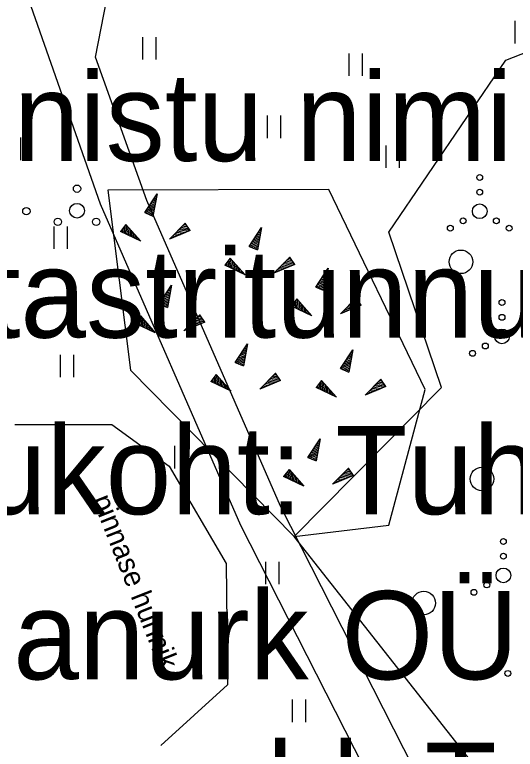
# Model space of a CAD drawing. Extents: x 554947 to 555436, y 6564938 to 6565792.
# Drawn here: x 555027.7 to 555044.71, y 6565611.19 to 6565636.15 of the extents above; entities that cross this region are included whole.
import ezdxf

# ---------------------------------------------------------------- set-up
doc = ezdxf.new("R2010")
doc.units = 0
for name, color, linetype in [('HALJASTUS', 7, 'Continuous'), ('KPKAABEL', 7, 'Continuous'), ('PR_SIDE', 7, 'Continuous'), ('PUU', 7, 'Continuous'), ('RELJEEF', 7, 'Continuous'), ('VORMISTUS_2', 7, 'Continuous')]:
    doc.layers.add(name, color=color, linetype=linetype)

msp = doc.modelspace()

# ---------------------------------------------------------------- linework, layer by layer
at = {"layer": 'HALJASTUS'}
for p, q in [((555044.7, 6565635.942), (555044.7, 6565635.181)), ((555032.047, 6565635.393), (555032.047, 6565634.632)), ((555032.502, 6565635.393), (555032.502, 6565634.632)), ((555039.053, 6565634.836), (555039.053, 6565634.075)), ((555039.508, 6565634.836), (555039.508, 6565634.075)), ((555036.276, 6565632.727), (555036.276, 6565631.965)), ((555036.731, 6565632.727), (555036.731, 6565631.965)), ((555027.9, 6565631.978), (555027.9, 6565631.217)), ((555040.315, 6565631.71), (555040.315, 6565630.949)), ((555040.77, 6565631.71), (555040.77, 6565630.949)), ((555029.028, 6565628.96), (555029.028, 6565628.199)), ((555029.483, 6565628.96), (555029.483, 6565628.199)), ((555029.243, 6565624.6), (555029.243, 6565623.839)), ((555029.698, 6565624.6), (555029.698, 6565623.839)), ((555033.134, 6565621.501), (555033.134, 6565620.74)), ((555033.589, 6565621.501), (555033.589, 6565620.74)), ((555036.221, 6565617.568), (555036.221, 6565616.807)), ((555036.676, 6565617.568), (555036.676, 6565616.807)), ((555037.132, 6565612.883), (555037.132, 6565612.122)), ((555037.587, 6565612.883), (555037.587, 6565612.122))]:
    msp.add_line(p, q, dxfattribs=at)
for points in [[(555057.023, 6565609.855), (555058.586, 6565605.616), (555058.613, 6565599.497), (555057.015, 6565597.532), (555043.839, 6565605.146), (555043.23, 6565610.761), (555037.198, 6565618.427), (555042.201, 6565623.493), (555040.415, 6565628.763), (555044.392, 6565634.613), (555048.032, 6565636.033)], [(555027.704, 6565622.233), (555030.999, 6565622.233), (555032.952, 6565620.81), (555034.891, 6565617.507), (555034.932, 6565613.389), (555032.663, 6565611.321)]]:
    msp.add_lwpolyline(points, dxfattribs=at)
for centre, radius in [((555043.503, 6565630.625), 0.1), ((555043.503, 6565630.125), 0.1), ((555043.503, 6565629.475), 0.25), ((555042.938, 6565629.15), 0.1), ((555044.068, 6565629.15), 0.1), ((555042.503, 6565628.9), 0.1), ((555044.503, 6565628.9), 0.1), ((555042.864, 6565627.758), 0.4), ((555044.26, 6565626.373), 0.1), ((555044.26, 6565625.873), 0.1), ((555044.26, 6565625.223), 0.25), ((555043.695, 6565624.898), 0.1), ((555043.26, 6565624.648), 0.1), ((555043.58, 6565620.38), 0.4), ((555044.307, 6565618.254), 0.1), ((555044.307, 6565617.754), 0.1), ((555044.307, 6565617.104), 0.25), ((555043.742, 6565616.779), 0.1), ((555043.307, 6565616.529), 0.1), ((555041.6, 6565616.164), 0.4), ((555044.458, 6565613.773), 0.1)]:
    msp.add_circle(centre, radius, dxfattribs=at)
at = {"layer": 'KPKAABEL'}
msp.add_lwpolyline([(555022.085, 6565654.913), (555021.622, 6565652.627), (555021.526, 6565649.765), (555022.786, 6565647.231), (555026.485, 6565641.465), (555030.606, 6565629.728), (555035.378, 6565618.813), (555040.844, 6565608.057), (555047.089, 6565597.805), (555053.567, 6565587.292), (555056.073, 6565583.696), (555062.108, 6565572.667), (555068.248, 6565560.982), (555073.771, 6565549.852), (555080.106, 6565537.978), (555085.958, 6565527.605), (555092.403, 6565515.607), (555098.402, 6565504.536), (555104.641, 6565492.438), (555110.839, 6565480.82), (555116.697, 6565469.072), (555121.821, 6565458.116), (555126.894, 6565446.731), (555132.737, 6565435.388)], dxfattribs=at)
at = {"layer": 'PR_SIDE'}
msp.add_lwpolyline([(555074.812, 6565550.025), (555070.293, 6565559.111), (555066.617, 6565567.361), (555061.392, 6565583.505), (555059.394, 6565594.411), (555058.991, 6565594.89), (555051.547, 6565599.57), (555045.662, 6565603.031), (555041.98, 6565609.132), (555036.735, 6565619.454), (555032.194, 6565629.84), (555030.448, 6565634.707), (555030.925, 6565637.158), (555034.991, 6565644.113), (555043.172, 6565658.105), (555043.563, 6565658.774), (555046.326, 6565658.494), (555056.182, 6565651.59), (555064.179, 6565647.804), (555084.437, 6565642.829), (555092.497, 6565648.433), (555092.737, 6565648.737), (555092.881, 6565649.42), (555093.272, 6565650.246)], dxfattribs=at)
at = {"layer": 'PUU'}
for centre, radius in [((555029.819, 6565630.243), 0.125), ((555028.098, 6565629.476), 0.125), ((555029.819, 6565629.493), 0.25), ((555029.169, 6565629.118), 0.125), ((555030.47, 6565629.118), 0.125)]:
    msp.add_circle(centre, radius, dxfattribs=at)
at = {"layer": 'RELJEEF'}
for p, q in [((555032.119, 6565629.429), (555032.539, 6565630.069)), ((555032.369, 6565629.804), (555032.499, 6565629.864)), ((555032.539, 6565630.069), (555032.399, 6565629.314)), ((555032.414, 6565629.879), (555032.514, 6565629.919)), ((555032.464, 6565629.954), (555032.524, 6565629.979)), ((555032.514, 6565630.029), (555032.534, 6565630.039)), ((555032.169, 6565629.504), (555032.454, 6565629.624)), ((555032.219, 6565629.579), (555032.469, 6565629.684)), ((555032.269, 6565629.654), (555032.394, 6565629.709)), ((555032.319, 6565629.729), (555032.489, 6565629.804)), ((555032.394, 6565629.709), (555032.479, 6565629.744)), ((555032.119, 6565629.429), (555032.444, 6565629.569)), ((555032.119, 6565629.429), (555032.399, 6565629.314)), ((555032.119, 6565629.429), (555032.119, 6565629.429)), ((555032.184, 6565629.404), (555032.434, 6565629.509)), ((555032.249, 6565629.374), (555032.424, 6565629.449)), ((555032.319, 6565629.349), (555032.414, 6565629.389)), ((555032.384, 6565629.324), (555032.399, 6565629.329)), ((555031.478, 6565629.028), (555031.293, 6565628.788)), ((555031.348, 6565628.858), (555031.363, 6565628.758)), ((555031.393, 6565628.918), (555031.418, 6565628.733)), ((555031.433, 6565628.973), (555031.468, 6565628.703)), ((555031.478, 6565629.028), (555031.983, 6565628.458)), ((555031.478, 6565629.028), (555031.523, 6565628.678)), ((555031.478, 6565629.028), (555031.478, 6565629.028)), ((555031.538, 6565628.963), (555031.578, 6565628.653)), ((555031.598, 6565628.893), (555031.633, 6565628.628)), ((555032.957, 6565628.523), (555033.497, 6565629.068)), ((555033.667, 6565628.818), (555033.317, 6565628.883)), ((555033.627, 6565628.873), (555033.362, 6565628.928)), ((555033.587, 6565628.933), (555033.402, 6565628.968)), ((555033.547, 6565628.993), (555033.447, 6565629.013)), ((555033.507, 6565629.053), (555033.487, 6565629.053)), ((555033.667, 6565628.818), (555033.497, 6565629.068)), ((555035.669, 6565628.282), (555036.089, 6565628.922)), ((555036.089, 6565628.922), (555035.949, 6565628.167)), ((555036.064, 6565628.882), (555036.084, 6565628.892)), ((555031.983, 6565628.458), (555031.293, 6565628.788)), ((555031.303, 6565628.803), (555031.308, 6565628.783)), ((555031.658, 6565628.828), (555031.673, 6565628.688)), ((555031.673, 6565628.688), (555031.688, 6565628.598)), ((555031.713, 6565628.758), (555031.743, 6565628.573)), ((555031.773, 6565628.693), (555031.793, 6565628.548)), ((555031.833, 6565628.623), (555031.848, 6565628.523)), ((555033.667, 6565628.818), (555032.957, 6565628.523)), ((555033.167, 6565628.608), (555033.062, 6565628.628)), ((555033.247, 6565628.643), (555033.107, 6565628.673)), ((555033.332, 6565628.678), (555033.147, 6565628.713)), ((555033.282, 6565628.738), (555033.192, 6565628.758)), ((555033.497, 6565628.748), (555033.232, 6565628.798)), ((555033.582, 6565628.783), (555033.277, 6565628.843)), ((555033.417, 6565628.713), (555033.282, 6565628.738)), ((555033.667, 6565628.818), (555033.667, 6565628.818)), ((555035.869, 6565628.582), (555036.039, 6565628.657)), ((555035.919, 6565628.657), (555036.049, 6565628.717)), ((555035.964, 6565628.732), (555036.064, 6565628.772)), ((555036.014, 6565628.807), (555036.074, 6565628.832)), ((555031.893, 6565628.558), (555031.903, 6565628.493)), ((555031.953, 6565628.488), (555031.958, 6565628.468)), ((555032.997, 6565628.538), (555032.982, 6565628.543)), ((555033.082, 6565628.573), (555033.022, 6565628.588)), ((555035.669, 6565628.282), (555035.994, 6565628.422)), ((555035.719, 6565628.357), (555036.004, 6565628.477)), ((555035.734, 6565628.257), (555035.984, 6565628.362)), ((555035.769, 6565628.432), (555036.019, 6565628.537)), ((555035.819, 6565628.507), (555035.944, 6565628.562)), ((555035.944, 6565628.562), (555036.029, 6565628.597)), ((555035.669, 6565628.282), (555035.949, 6565628.167)), ((555035.669, 6565628.282), (555035.669, 6565628.282)), ((555035.799, 6565628.227), (555035.974, 6565628.302)), ((555035.869, 6565628.202), (555035.964, 6565628.242)), ((555035.934, 6565628.177), (555035.949, 6565628.182)), ((555035.028, 6565627.881), (555034.843, 6565627.641)), ((555035.028, 6565627.881), (555035.533, 6565627.311)), ((555035.028, 6565627.881), (555035.073, 6565627.531)), ((555035.028, 6565627.881), (555035.028, 6565627.881)), ((555036.507, 6565627.376), (555037.047, 6565627.921)), ((555037.097, 6565627.846), (555036.997, 6565627.866)), ((555037.057, 6565627.906), (555037.037, 6565627.906)), ((555037.217, 6565627.671), (555037.047, 6565627.921)), ((555035.533, 6565627.311), (555034.843, 6565627.641)), ((555034.853, 6565627.656), (555034.858, 6565627.636)), ((555034.898, 6565627.711), (555034.913, 6565627.611)), ((555034.943, 6565627.771), (555034.968, 6565627.586)), ((555034.983, 6565627.826), (555035.018, 6565627.556)), ((555035.088, 6565627.816), (555035.128, 6565627.506)), ((555035.148, 6565627.746), (555035.183, 6565627.481)), ((555035.208, 6565627.681), (555035.223, 6565627.541)), ((555035.263, 6565627.611), (555035.293, 6565627.426)), ((555037.217, 6565627.671), (555036.507, 6565627.376)), ((555036.832, 6565627.591), (555036.742, 6565627.611)), ((555037.047, 6565627.601), (555036.782, 6565627.651)), ((555037.132, 6565627.636), (555036.827, 6565627.696)), ((555037.217, 6565627.671), (555036.867, 6565627.736)), ((555037.177, 6565627.726), (555036.912, 6565627.781)), ((555037.137, 6565627.786), (555036.952, 6565627.821)), ((555037.217, 6565627.671), (555037.217, 6565627.671)), ((555035.223, 6565627.541), (555035.238, 6565627.451)), ((555035.323, 6565627.546), (555035.343, 6565627.401)), ((555035.383, 6565627.476), (555035.398, 6565627.376)), ((555035.443, 6565627.411), (555035.453, 6565627.346)), ((555036.547, 6565627.391), (555036.532, 6565627.396)), ((555036.632, 6565627.426), (555036.572, 6565627.441)), ((555036.717, 6565627.461), (555036.612, 6565627.481)), ((555036.797, 6565627.496), (555036.657, 6565627.526)), ((555036.882, 6565627.531), (555036.697, 6565627.566)), ((555036.967, 6565627.566), (555036.832, 6565627.591)), ((555037.932, 6565626.897), (555038.352, 6565627.537)), ((555038.352, 6565627.537), (555038.212, 6565626.782)), ((555038.227, 6565627.347), (555038.327, 6565627.387)), ((555038.277, 6565627.422), (555038.337, 6565627.447)), ((555038.327, 6565627.497), (555038.347, 6565627.507)), ((555035.503, 6565627.341), (555035.508, 6565627.321)), ((555038.032, 6565627.047), (555038.282, 6565627.152)), ((555038.082, 6565627.122), (555038.207, 6565627.177)), ((555038.132, 6565627.197), (555038.302, 6565627.272)), ((555038.182, 6565627.272), (555038.312, 6565627.332)), ((555038.207, 6565627.177), (555038.292, 6565627.212)), ((555032.612, 6565626.32), (555033.032, 6565626.96)), ((555033.032, 6565626.96), (555032.892, 6565626.205)), ((555032.957, 6565626.845), (555033.017, 6565626.87)), ((555033.007, 6565626.92), (555033.027, 6565626.93)), ((555037.932, 6565626.897), (555038.257, 6565627.037)), ((555037.932, 6565626.897), (555038.212, 6565626.782)), ((555037.932, 6565626.897), (555037.932, 6565626.897)), ((555037.982, 6565626.972), (555038.267, 6565627.092)), ((555037.997, 6565626.872), (555038.247, 6565626.977)), ((555038.062, 6565626.842), (555038.237, 6565626.917)), ((555038.132, 6565626.817), (555038.227, 6565626.857)), ((555032.812, 6565626.62), (555032.982, 6565626.695)), ((555032.862, 6565626.695), (555032.992, 6565626.755)), ((555032.887, 6565626.6), (555032.972, 6565626.635)), ((555032.907, 6565626.77), (555033.007, 6565626.81)), ((555038.197, 6565626.792), (555038.212, 6565626.797)), ((555032.612, 6565626.32), (555032.937, 6565626.46)), ((555032.662, 6565626.395), (555032.947, 6565626.515)), ((555032.677, 6565626.295), (555032.927, 6565626.4)), ((555032.712, 6565626.47), (555032.962, 6565626.575)), ((555032.762, 6565626.545), (555032.887, 6565626.6)), ((555037.291, 6565626.496), (555037.106, 6565626.256)), ((555037.206, 6565626.386), (555037.231, 6565626.201)), ((555037.246, 6565626.441), (555037.281, 6565626.171)), ((555037.291, 6565626.496), (555037.796, 6565625.926)), ((555037.291, 6565626.496), (555037.336, 6565626.146)), ((555037.291, 6565626.496), (555037.291, 6565626.496)), ((555037.351, 6565626.431), (555037.391, 6565626.121)), ((555037.411, 6565626.361), (555037.446, 6565626.096)), ((555038.77, 6565625.991), (555039.31, 6565626.536)), ((555039.44, 6565626.341), (555039.175, 6565626.396)), ((555039.4, 6565626.401), (555039.215, 6565626.436)), ((555039.36, 6565626.461), (555039.26, 6565626.481)), ((555039.32, 6565626.521), (555039.3, 6565626.521)), ((555039.48, 6565626.286), (555039.31, 6565626.536)), ((555032.612, 6565626.32), (555032.892, 6565626.205)), ((555032.612, 6565626.32), (555032.612, 6565626.32)), ((555032.742, 6565626.265), (555032.917, 6565626.34)), ((555032.812, 6565626.24), (555032.907, 6565626.28)), ((555032.877, 6565626.215), (555032.892, 6565626.22)), ((555037.796, 6565625.926), (555037.106, 6565626.256)), ((555037.116, 6565626.271), (555037.121, 6565626.251)), ((555037.161, 6565626.326), (555037.176, 6565626.226)), ((555037.471, 6565626.296), (555037.486, 6565626.156)), ((555037.486, 6565626.156), (555037.501, 6565626.066)), ((555037.526, 6565626.226), (555037.556, 6565626.041)), ((555037.586, 6565626.161), (555037.606, 6565626.016)), ((555039.48, 6565626.286), (555038.77, 6565625.991)), ((555039.06, 6565626.111), (555038.92, 6565626.141)), ((555039.145, 6565626.146), (555038.96, 6565626.181)), ((555039.095, 6565626.206), (555039.005, 6565626.226)), ((555039.31, 6565626.216), (555039.045, 6565626.266)), ((555039.395, 6565626.251), (555039.09, 6565626.311)), ((555039.23, 6565626.181), (555039.095, 6565626.206)), ((555039.48, 6565626.286), (555039.13, 6565626.351)), ((555039.48, 6565626.286), (555039.48, 6565626.286)), ((555031.971, 6565625.919), (555031.786, 6565625.679)), ((555031.926, 6565625.864), (555031.961, 6565625.594)), ((555031.971, 6565625.919), (555032.476, 6565625.349)), ((555031.971, 6565625.919), (555032.016, 6565625.569)), ((555031.971, 6565625.919), (555031.971, 6565625.919)), ((555033.45, 6565625.414), (555033.99, 6565625.959)), ((555034.08, 6565625.824), (555033.895, 6565625.859)), ((555034.04, 6565625.884), (555033.94, 6565625.904)), ((555034, 6565625.944), (555033.98, 6565625.944)), ((555034.16, 6565625.709), (555033.99, 6565625.959)), ((555037.646, 6565626.091), (555037.661, 6565625.991)), ((555037.706, 6565626.026), (555037.716, 6565625.961)), ((555037.766, 6565625.956), (555037.771, 6565625.936)), ((555038.81, 6565626.006), (555038.795, 6565626.011)), ((555038.895, 6565626.041), (555038.835, 6565626.056)), ((555038.98, 6565626.076), (555038.875, 6565626.096)), ((555032.476, 6565625.349), (555031.786, 6565625.679)), ((555031.796, 6565625.694), (555031.801, 6565625.674)), ((555031.841, 6565625.749), (555031.856, 6565625.649)), ((555031.886, 6565625.809), (555031.911, 6565625.624)), ((555032.031, 6565625.854), (555032.071, 6565625.544)), ((555032.091, 6565625.784), (555032.126, 6565625.519)), ((555032.151, 6565625.719), (555032.166, 6565625.579)), ((555032.206, 6565625.649), (555032.236, 6565625.464)), ((555034.16, 6565625.709), (555033.45, 6565625.414)), ((555033.775, 6565625.629), (555033.685, 6565625.649)), ((555033.99, 6565625.639), (555033.725, 6565625.689)), ((555034.075, 6565625.674), (555033.77, 6565625.734)), ((555033.91, 6565625.604), (555033.775, 6565625.629)), ((555034.16, 6565625.709), (555033.81, 6565625.774)), ((555034.12, 6565625.764), (555033.855, 6565625.819)), ((555034.16, 6565625.709), (555034.16, 6565625.709)), ((555032.166, 6565625.579), (555032.181, 6565625.489)), ((555032.266, 6565625.584), (555032.286, 6565625.439)), ((555032.326, 6565625.514), (555032.341, 6565625.414)), ((555032.386, 6565625.449), (555032.396, 6565625.384)), ((555032.446, 6565625.379), (555032.451, 6565625.359)), ((555033.49, 6565625.429), (555033.475, 6565625.434)), ((555033.575, 6565625.464), (555033.515, 6565625.479)), ((555033.66, 6565625.499), (555033.555, 6565625.519)), ((555033.74, 6565625.534), (555033.6, 6565625.564)), ((555033.825, 6565625.569), (555033.64, 6565625.604)), ((555035.191, 6565624.335), (555035.611, 6565624.975)), ((555035.611, 6565624.975), (555035.471, 6565624.22)), ((555035.536, 6565624.86), (555035.596, 6565624.885)), ((555035.586, 6565624.935), (555035.606, 6565624.945)), ((555035.341, 6565624.56), (555035.466, 6565624.615)), ((555035.391, 6565624.635), (555035.561, 6565624.71)), ((555035.441, 6565624.71), (555035.571, 6565624.77)), ((555035.466, 6565624.615), (555035.551, 6565624.65)), ((555035.486, 6565624.785), (555035.586, 6565624.825)), ((555038.77, 6565624.129), (555039.19, 6565624.769)), ((555039.19, 6565624.769), (555039.05, 6565624.014)), ((555039.065, 6565624.579), (555039.165, 6565624.619)), ((555039.115, 6565624.654), (555039.175, 6565624.679)), ((555039.165, 6565624.729), (555039.185, 6565624.739)), ((555035.191, 6565624.335), (555035.516, 6565624.475)), ((555035.241, 6565624.41), (555035.526, 6565624.53)), ((555035.256, 6565624.31), (555035.506, 6565624.415)), ((555035.291, 6565624.485), (555035.541, 6565624.59)), ((555038.87, 6565624.279), (555039.12, 6565624.384)), ((555038.92, 6565624.354), (555039.045, 6565624.409)), ((555038.97, 6565624.429), (555039.14, 6565624.504)), ((555039.02, 6565624.504), (555039.15, 6565624.564)), ((555039.045, 6565624.409), (555039.13, 6565624.444)), ((555035.191, 6565624.335), (555035.471, 6565624.22)), ((555035.191, 6565624.335), (555035.191, 6565624.335)), ((555035.321, 6565624.28), (555035.496, 6565624.355)), ((555035.391, 6565624.255), (555035.486, 6565624.295)), ((555035.456, 6565624.23), (555035.471, 6565624.235)), ((555038.77, 6565624.129), (555039.095, 6565624.269)), ((555038.77, 6565624.129), (555039.05, 6565624.014)), ((555038.77, 6565624.129), (555038.77, 6565624.129)), ((555038.82, 6565624.204), (555039.105, 6565624.324)), ((555038.835, 6565624.104), (555039.085, 6565624.209)), ((555038.9, 6565624.074), (555039.075, 6565624.149)), ((555034.549, 6565623.934), (555034.364, 6565623.694)), ((555034.504, 6565623.879), (555034.539, 6565623.609)), ((555034.549, 6565623.934), (555035.054, 6565623.364)), ((555034.549, 6565623.934), (555034.594, 6565623.584)), ((555034.549, 6565623.934), (555034.549, 6565623.934)), ((555034.609, 6565623.869), (555034.649, 6565623.559)), ((555036.029, 6565623.429), (555036.569, 6565623.974)), ((555036.659, 6565623.839), (555036.474, 6565623.874)), ((555036.619, 6565623.899), (555036.519, 6565623.919)), ((555036.579, 6565623.959), (555036.559, 6565623.959)), ((555036.739, 6565623.724), (555036.569, 6565623.974)), ((555038.97, 6565624.049), (555039.065, 6565624.089)), ((555039.035, 6565624.024), (555039.05, 6565624.029)), ((555035.054, 6565623.364), (555034.364, 6565623.694)), ((555034.374, 6565623.709), (555034.379, 6565623.689)), ((555034.419, 6565623.764), (555034.434, 6565623.664)), ((555034.464, 6565623.824), (555034.489, 6565623.639)), ((555034.669, 6565623.799), (555034.704, 6565623.534)), ((555034.729, 6565623.734), (555034.744, 6565623.594)), ((555034.784, 6565623.664), (555034.814, 6565623.479)), ((555036.739, 6565623.724), (555036.029, 6565623.429)), ((555036.404, 6565623.584), (555036.219, 6565623.619)), ((555036.354, 6565623.644), (555036.264, 6565623.664)), ((555036.569, 6565623.654), (555036.304, 6565623.704)), ((555036.654, 6565623.689), (555036.349, 6565623.749)), ((555036.489, 6565623.619), (555036.354, 6565623.644)), ((555036.739, 6565623.724), (555036.389, 6565623.789)), ((555036.699, 6565623.779), (555036.434, 6565623.834)), ((555036.739, 6565623.724), (555036.739, 6565623.724)), ((555038.128, 6565623.728), (555037.943, 6565623.488)), ((555038.043, 6565623.618), (555038.068, 6565623.433)), ((555038.083, 6565623.673), (555038.118, 6565623.403)), ((555038.128, 6565623.728), (555038.633, 6565623.158)), ((555038.128, 6565623.728), (555038.173, 6565623.378)), ((555038.128, 6565623.728), (555038.128, 6565623.728)), ((555038.188, 6565623.663), (555038.228, 6565623.353)), ((555039.608, 6565623.223), (555040.148, 6565623.768)), ((555040.278, 6565623.573), (555040.013, 6565623.628)), ((555040.238, 6565623.633), (555040.053, 6565623.668)), ((555040.198, 6565623.693), (555040.098, 6565623.713)), ((555040.158, 6565623.753), (555040.138, 6565623.753)), ((555040.318, 6565623.518), (555040.148, 6565623.768)), ((555034.744, 6565623.594), (555034.759, 6565623.504)), ((555034.844, 6565623.599), (555034.864, 6565623.454)), ((555034.904, 6565623.529), (555034.919, 6565623.429)), ((555034.964, 6565623.464), (555034.974, 6565623.399)), ((555035.024, 6565623.394), (555035.029, 6565623.374)), ((555036.069, 6565623.444), (555036.054, 6565623.449)), ((555036.154, 6565623.479), (555036.094, 6565623.494)), ((555036.239, 6565623.514), (555036.134, 6565623.534)), ((555036.319, 6565623.549), (555036.179, 6565623.579)), ((555038.633, 6565623.158), (555037.943, 6565623.488)), ((555037.953, 6565623.503), (555037.958, 6565623.483)), ((555037.998, 6565623.558), (555038.013, 6565623.458)), ((555038.248, 6565623.593), (555038.283, 6565623.328)), ((555038.308, 6565623.528), (555038.323, 6565623.388)), ((555038.323, 6565623.388), (555038.338, 6565623.298)), ((555038.363, 6565623.458), (555038.393, 6565623.273)), ((555038.423, 6565623.393), (555038.443, 6565623.248)), ((555040.318, 6565623.518), (555039.608, 6565623.223)), ((555039.898, 6565623.343), (555039.758, 6565623.373)), ((555039.983, 6565623.378), (555039.798, 6565623.413)), ((555039.933, 6565623.438), (555039.843, 6565623.458)), ((555040.148, 6565623.448), (555039.883, 6565623.498)), ((555040.233, 6565623.483), (555039.928, 6565623.543)), ((555040.068, 6565623.413), (555039.933, 6565623.438)), ((555040.318, 6565623.518), (555039.968, 6565623.583)), ((555040.318, 6565623.518), (555040.318, 6565623.518)), ((555038.483, 6565623.323), (555038.498, 6565623.223)), ((555038.543, 6565623.258), (555038.553, 6565623.193)), ((555038.603, 6565623.188), (555038.608, 6565623.168)), ((555039.648, 6565623.238), (555039.633, 6565623.243)), ((555039.733, 6565623.273), (555039.673, 6565623.288)), ((555039.818, 6565623.308), (555039.713, 6565623.328)), ((555037.666, 6565621.106), (555038.086, 6565621.746)), ((555038.086, 6565621.746), (555037.946, 6565620.991)), ((555038.011, 6565621.631), (555038.071, 6565621.656)), ((555038.061, 6565621.706), (555038.081, 6565621.716)), ((555037.816, 6565621.331), (555037.941, 6565621.386)), ((555037.866, 6565621.406), (555038.036, 6565621.481)), ((555037.916, 6565621.481), (555038.046, 6565621.541)), ((555037.941, 6565621.386), (555038.026, 6565621.421)), ((555037.961, 6565621.556), (555038.061, 6565621.596)), ((555037.666, 6565621.106), (555037.991, 6565621.246)), ((555037.716, 6565621.181), (555038.001, 6565621.301)), ((555037.731, 6565621.081), (555037.981, 6565621.186)), ((555037.766, 6565621.256), (555038.016, 6565621.361)), ((555037.796, 6565621.051), (555037.971, 6565621.126)), ((555037.666, 6565621.106), (555037.946, 6565620.991)), ((555037.666, 6565621.106), (555037.666, 6565621.106)), ((555037.866, 6565621.026), (555037.961, 6565621.066)), ((555037.931, 6565621.001), (555037.946, 6565621.006)), ((555037.025, 6565620.705), (555036.84, 6565620.465)), ((555036.98, 6565620.65), (555037.015, 6565620.38)), ((555037.025, 6565620.705), (555037.53, 6565620.135)), ((555037.025, 6565620.705), (555037.07, 6565620.355)), ((555037.025, 6565620.705), (555037.025, 6565620.705)), ((555037.085, 6565620.64), (555037.125, 6565620.33)), ((555038.504, 6565620.2), (555039.044, 6565620.745)), ((555039.134, 6565620.61), (555038.949, 6565620.645)), ((555039.094, 6565620.67), (555038.994, 6565620.69)), ((555039.054, 6565620.73), (555039.034, 6565620.73)), ((555039.214, 6565620.495), (555039.044, 6565620.745)), ((555037.53, 6565620.135), (555036.84, 6565620.465)), ((555036.85, 6565620.48), (555036.855, 6565620.46)), ((555036.895, 6565620.535), (555036.91, 6565620.435)), ((555036.94, 6565620.595), (555036.965, 6565620.41)), ((555037.145, 6565620.57), (555037.18, 6565620.305)), ((555037.205, 6565620.505), (555037.22, 6565620.365)), ((555037.26, 6565620.435), (555037.29, 6565620.25)), ((555037.32, 6565620.37), (555037.34, 6565620.225)), ((555039.214, 6565620.495), (555038.504, 6565620.2)), ((555038.879, 6565620.355), (555038.694, 6565620.39)), ((555038.829, 6565620.415), (555038.739, 6565620.435)), ((555039.044, 6565620.425), (555038.779, 6565620.475)), ((555039.129, 6565620.46), (555038.824, 6565620.52)), ((555038.964, 6565620.39), (555038.829, 6565620.415)), ((555039.214, 6565620.495), (555038.864, 6565620.56)), ((555039.174, 6565620.55), (555038.909, 6565620.605)), ((555039.214, 6565620.495), (555039.214, 6565620.495)), ((555037.22, 6565620.365), (555037.235, 6565620.275)), ((555037.38, 6565620.3), (555037.395, 6565620.2)), ((555037.44, 6565620.235), (555037.45, 6565620.17)), ((555037.5, 6565620.165), (555037.505, 6565620.145)), ((555038.544, 6565620.215), (555038.529, 6565620.22)), ((555038.629, 6565620.25), (555038.569, 6565620.265)), ((555038.714, 6565620.285), (555038.609, 6565620.305)), ((555038.794, 6565620.32), (555038.654, 6565620.35))]:
    msp.add_line(p, q, dxfattribs=at)
msp.add_lwpolyline([(555030.863, 6565630.19), (555031.632, 6565624.071), (555037.198, 6565618.427), (555040.417, 6565618.809), (555041.648, 6565623.42), (555038.371, 6565630.217)], close=True, dxfattribs=at)

# ---------------------------------------------------------------- texts
at = {"layer": 'HALJASTUS'}
msp.add_text('pinnase hunnik', height=0.7, rotation=291.6863, dxfattribs=at).set_placement((555030.325, 6565619.69))
at = {"layer": 'VORMISTUS_2'}
for s, p in [('Kinnistu nimi: 11202 Vaida-Urge tee', (555021.874, 6565631.182)), ('Katastritunnus: 33701:001:0541', (555021.874, 6565625.182)), ('Asukoht: Tuhala küla, Kose vald, Harju maakond', (555021.874, 6565619.182))]:
    msp.add_text(s, height=3, dxfattribs=at).set_placement(p)
for s, p in [('Kirjanurk OÜ töö nr 10379P', (555021.859, 6565613.572)), ('Kose vald, Tuhala ja Otiveski elurajooni sideühendus', (555021.782, 6565608.425))]:
    msp.add_text(s, height=3, rotation=360, dxfattribs=at).set_placement(p)

doc.saveas('drawing.dxf')
